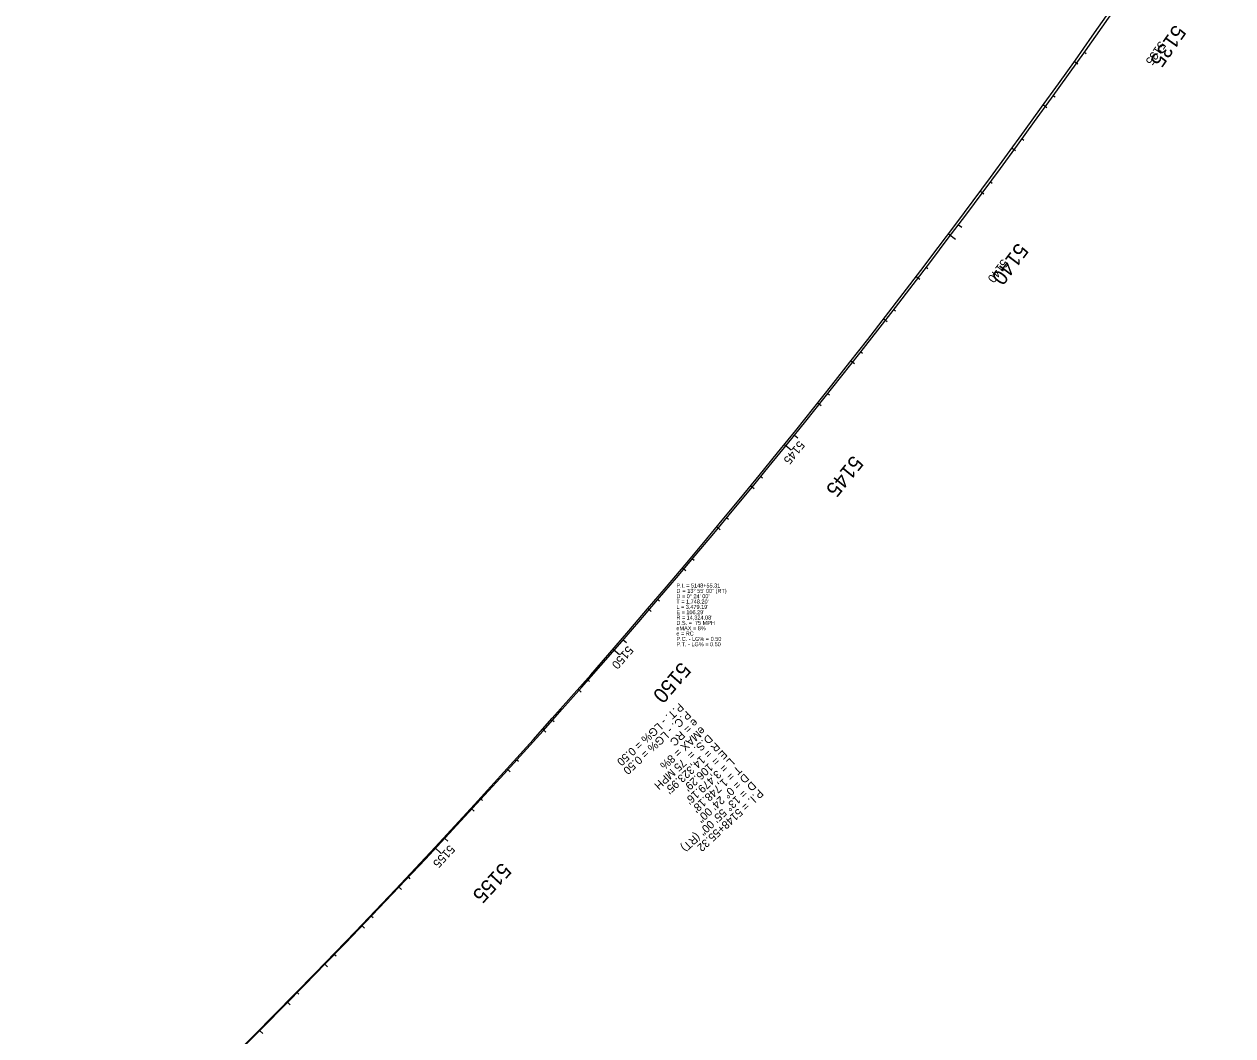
# Model space of a CAD drawing. Extents: x 2160876 to 2175990, y 601436 to 618246.
# Drawn here: x 2172654 to 2174919, y 614536 to 616431 of the extents above; entities that cross this region are included whole.
import ezdxf

# ---------------------------------------------------------------- set-up
doc = ezdxf.new("R2010")
doc.units = 0
for name, color, linetype in [('BNDY-ADJ', 7, 'Continuous'), ('RD_DTM_Major2', 7, 'Continuous'), ('RD_EX_BldgApp_Steps', 7, 'Continuous'), ('RD_EX_DV_TX_Prop', 7, 'Continuous'), ('RD_EX_Parking_Conc', 7, 'Continuous')]:
    doc.layers.add(name, color=color, linetype=linetype)

msp = doc.modelspace()

# ---------------------------------------------------------------- linework, layer by layer
at = {"layer": 'BNDY-ADJ'}
msp.add_arc((2162936.5, 624645.9), 14323.9, 312.71947, 326.63611, dxfattribs=at)
at = {"layer": 'RD_DTM_Major2'}
for p, q in [((2174621.7, 616361.5), (2174628.3, 616356.8)), ((2174563.6, 616280.1), (2174570.1, 616275.4)), ((2174504.9, 616199.1), (2174511.4, 616194.4)), ((2174445.7, 616118.6), (2174452.1, 616113.8)), ((2174385.9, 616038.4), (2174398.7, 616028.8)), ((2174325.5, 615958.7), (2174331.9, 615953.9)), ((2174264.6, 615879.4), (2174270.9, 615874.5)), ((2174203.1, 615800.5), (2174209.4, 615795.6)), ((2174141.1, 615722.1), (2174147.3, 615717.1)), ((2174078.5, 615644.1), (2174090.9, 615634)), ((2174015.4, 615566.5), (2174021.6, 615561.5)), ((2173951.7, 615489.4), (2173957.9, 615484.3)), ((2173887.5, 615412.7), (2173893.6, 615407.6)), ((2173822.8, 615336.5), (2173828.9, 615331.3)), ((2173757.5, 615260.7), (2173769.6, 615250.2)), ((2173691.8, 615185.4), (2173697.8, 615180.1)), ((2173625.5, 615110.6), (2173631.4, 615105.2)), ((2173558.6, 615036.2), (2173564.6, 615030.8)), ((2173491.3, 614962.2), (2173497.2, 614956.8)), ((2173423.4, 614888.8), (2173435.1, 614877.9)), ((2173355, 614815.8), (2173360.9, 614810.3)), ((2173286.2, 614743.3), (2173291.9, 614737.8)), ((2173216.8, 614671.3), (2173222.5, 614665.7)), ((2173146.9, 614599.8), (2173152.6, 614594.2))]:
    msp.add_line(p, q, dxfattribs=at)
at = {"layer": 'RD_EX_BldgApp_Steps'}
for p, q in [((2174640.4, 616378.7), (2174643.7, 616376.4)), ((2174582.3, 616297.4), (2174585.6, 616295)), ((2174523.6, 616216.4), (2174526.9, 616214)), ((2174464.4, 616135.8), (2174467.6, 616133.5)), ((2174404.6, 616055.7), (2174411, 616050.9)), ((2174344.2, 615976), (2174347.4, 615973.5)), ((2174283.3, 615896.7), (2174286.4, 615894.2)), ((2174221.8, 615817.8), (2174224.9, 615815.3)), ((2174159.8, 615739.4), (2174162.9, 615736.9)), ((2174097.2, 615661.4), (2174103.4, 615656.3)), ((2174034.1, 615583.8), (2174037.2, 615581.3)), ((2173970.4, 615506.7), (2173973.5, 615504.1)), ((2173906.2, 615430), (2173909.3, 615427.4)), ((2173841.5, 615353.8), (2173844.5, 615351.2)), ((2173776.3, 615278), (2173782.3, 615272.8)), ((2173710.5, 615202.7), (2173713.5, 615200)), ((2173644.2, 615127.8), (2173647.1, 615125.2)), ((2173577.3, 615053.4), (2173580.3, 615050.8)), ((2173510, 614979.5), (2173512.9, 614976.8)), ((2173442.1, 614906.1), (2173448, 614900.6)), ((2173373.8, 614833.1), (2173376.7, 614830.3)), ((2173304.9, 614760.6), (2173307.8, 614757.8)), ((2173235.5, 614688.6), (2173238.4, 614685.8)), ((2173165.6, 614617.1), (2173168.5, 614614.3)), ((2173095.2, 614546), (2173100.9, 614540.4))]:
    msp.add_line(p, q, dxfattribs=at)
msp.add_arc((2162955.1, 624663.2), 14324.1, 312.71947, 326.63611, dxfattribs=at)

# ---------------------------------------------------------------- texts
for s, rotation, p in [('5135', 235.0646, (2174809.9, 616432.1)), ('5140', 233.0646, (2174515.4, 616023.4)), ('5145', 231.0646, (2174206.8, 615625.2)), ('5150', 229.0646, (2173884.6, 615238.1)), ('5155', 227.0646, (2173548.9, 614862.3))]:
    msp.add_text(s, height=28, rotation=rotation, dxfattribs=at).set_placement(p)
for s, p in [('P.I. = 5148+55.31', (2173876, 615376)), ('D', (2173876, 615366)), ('D = 0° 24\' 00"', (2173876, 615356)), ('    = 13° 55\' 00" (RT)', (2173876, 615366)), ("T = 1,748.20'", (2173876, 615346)), ("L = 3,479.19'", (2173876, 615336)), ("E = 106.29'", (2173876, 615326)), ("R = 14,324.08'", (2173876, 615316)), ('D.S. =  75 MPH ', (2173876, 615306)), ('eMAX = 8%', (2173876, 615296)), ('e = RC', (2173876, 615286)), ('P.C. - LG% = 0.50', (2173876, 615276)), ('P.T. - LG% = 0.50', (2173876, 615266))]:
    msp.add_text(s, height=7.5, dxfattribs=at).set_placement(p)
at = {"layer": 'RD_EX_DV_TX_Prop'}
for s, rotation, p in [('5135', 235.0647, (2174781.4, 616400.8)), ('5140', 233.0647, (2174486.7, 615992.8)), ('5145', 231.0647, (2174105.6, 615652.1)), ('5150', 229.0647, (2173784.9, 615267.9)), ('5155', 227.0647, (2173451, 614894.9))]:
    msp.add_text(s, height=16, rotation=rotation, dxfattribs=at).set_placement(p)
at = {"layer": 'RD_EX_Parking_Conc'}
for s, p in [('P.T. - LG% = 0.50', (2173881.6, 615160.7)), ('P.C. - LG% = 0.50', (2173895.1, 615146)), ('eMAX = 8%', (2173922.3, 615116.6)), ('e = RC', (2173908.7, 615131.3)), ('D.S. =  75 MPH', (2173935.9, 615101.9)), ("R = 14,323.95'", (2173949.4, 615087.2)), ("E = 106.29'", (2173963, 615072.5)), ("L = 3,479.16'", (2173976.6, 615057.8)), ("T = 1,748.18'", (2173990.1, 615043.1)), ('D = 0° 24\' 00"', (2174003.7, 615028.5)), ('    = 13° 55\' 00" (RT)', (2174017.3, 615013.8)), ('P.I. = 5148+55.32', (2174030.8, 614999.1)), ('D', (2174017.3, 615013.8))]:
    msp.add_text(s, height=15, rotation=222.7195, dxfattribs=at).set_placement(p)

doc.saveas('drawing.dxf')
